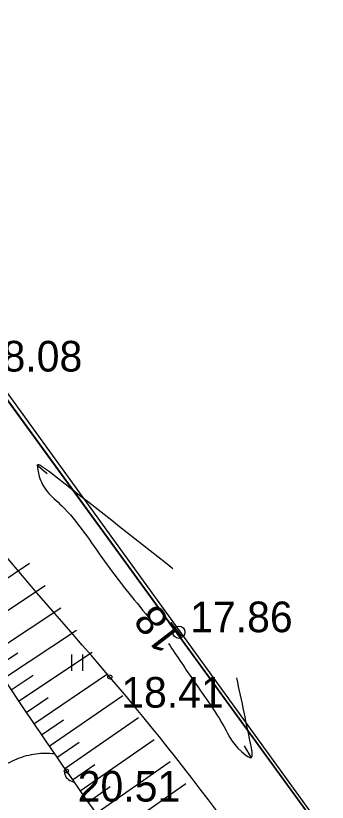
# Model space of a CAD drawing. Extents: x 521824 to 524158, y 294774 to 296228.
# Drawn here: x 522313.44 to 522324.88, y 296028.68 to 296057.55 of the extents above; entities that cross this region are included whole.
import ezdxf

# ---------------------------------------------------------------- set-up
doc = ezdxf.new("R2010")
doc.units = 0
for name, color, linetype in [('HIDG_AATZ_####_TKST_#', 7, 'Continuous'), ('HIDG_ELEM_####_####_#', 7, 'Continuous'), ('HIDG_HORZ_####_TKST_#', 7, 'Continuous'), ('HIDG_HORZ_RESN_####_#', 7, 'Continuous'), ('HIDG_PLIN_####_####_#', 7, 'Continuous'), ('RAMI_UZMR_####_####_#', 7, 'Continuous'), ('RELJ_AATZ_####_TKST_#', 7, 'Continuous'), ('RELJ_ELEM_####_####_#', 7, 'Continuous'), ('RELJ_HORZ_PAMT_####_#', 7, 'Continuous'), ('RELJ_HORZ_RESN_####_#', 7, 'Continuous'), ('RELJ_NOGA_####_####_#', 7, 'Continuous'), ('ROBZ_IERR_####_####_#', 7, 'Continuous'), ('TERT_ELEM_####_####_#', 7, 'Continuous')]:
    doc.layers.add(name, color=color, linetype=linetype)

msp = doc.modelspace()

# ---------------------------------------------------------------- linework, layer by layer
at = {"layer": 'HIDG_ELEM_####_####_#'}
msp.add_circle((522319.429, 296034.919), 0.225, dxfattribs=at)
at = {"layer": 'HIDG_HORZ_RESN_####_#'}
for p, q in [((522314.599, 296040.729), (522314.217, 296041.051)), ((522321.835, 296030.742), (522322.089, 296030.311))]:
    msp.add_line(p, q, dxfattribs=at)
for points in [[(522319.216, 296037.249), (522314.68, 296040.801), (522314.532, 296040.912), (522314.414, 296040.992), (522314.259, 296041.062), (522314.248, 296040.884), (522315.133, 296039.559), (522316.698, 296037.525), (522318.305, 296035.484)], [(522319.05, 296034.51), (522320.017, 296033.073), (522321.092, 296031.449), (522321.907, 296030.397), (522322.102, 296030.323), (522322.126, 296030.441), (522322.118, 296030.543), (522322.094, 296030.677), (522321.559, 296033.239)]]:
    msp.add_spline(points, degree=3, dxfattribs=at)
at = {"layer": 'HIDG_PLIN_####_####_#'}
msp.add_spline([(522371.644, 295960.784), (522368.316, 295964.419), (522361.623, 295972.484), (522354.568, 295982.304), (522351.14, 295981.353), (522353.628, 295983.369), (522349.258, 295989.963), (522348.612, 295994.653), (522338.197, 296003.541), (522326.066, 296020.438), (522316.898, 296033.274), (522306.811, 296047.683), (522300.907, 296055.765), (522298.65, 296054.773), (522297.679, 296054.56), (522296.95, 296056.439), (522297.579, 296057.714), (522297.352, 296058.697), (522297.043, 296059.475), (522296.096, 296061.4), (522294.24, 296064.18)], degree=3, dxfattribs=at)
at = {"layer": 'RAMI_UZMR_####_####_#'}
msp.add_lwpolyline([(522238.336, 296053.36), (522285.718, 296059.481), (522293.257, 296061.848), (522296.155, 296062.191), (522300.201, 296058.476), (522312.508, 296044.556), (522328.24, 296022.822), (522349.854, 295994.636), (522373.592, 295961.698), (522362.138, 295957.162), (522349.174, 295950.882), (522342.278, 295948.544), (522332.736, 295938.071), (522327.686, 295933.811), (522322.022, 295927.668), (522307.813, 295919.973), (522290.212, 295909.174), (522273.707, 295894.679), (522210.195, 295852.819)], dxfattribs=at)
at = {"layer": 'RELJ_ELEM_####_####_#'}
for centre in [(522316.898, 296033.274), (522315.3, 296029.826)]:
    msp.add_circle(centre, 0.075, dxfattribs=at)
at = {"layer": 'RELJ_HORZ_PAMT_####_#'}
msp.add_spline([(522315.604, 296029.396), (522315.24, 296029.699), (522315.251, 296029.819), (522315.303, 296029.833), (522315.332, 296029.807), (522315.604, 296029.396)], degree=3, dxfattribs=at)
at = {"layer": 'RELJ_HORZ_RESN_####_#'}
msp.add_spline([(522314.864, 296030.455), (522314.186, 296030.447), (522313.483, 296030.257), (522312.807, 296029.903), (522312.495, 296029.672), (522312.211, 296029.408), (522311.403, 296028.4), (522311.062, 296027.851), (522310.752, 296027.266), (522310.302, 296026.082), (522310.051, 296024.862), (522309.959, 296023.658), (522310.068, 296022.457), (522310.766, 296020.31), (522311.406, 296019.168), (522312.083, 296018.156)], degree=3, dxfattribs=at)
at = {"layer": 'RELJ_NOGA_####_####_#'}
for p, q in [((522311.339, 296035.722), (522313.945, 296037.455)), ((522311.891, 296034.889), (522314.525, 296036.629)), ((522312.443, 296034.054), (522315.101, 296035.81)), ((522312.994, 296033.22), (522315.676, 296034.995)), ((522312.718, 296033.637), (522313.519, 296034.167)), ((522313.548, 296032.388), (522316.246, 296034.191)), ((522313.271, 296032.803), (522314.078, 296033.34)), ((522314.108, 296031.559), (522316.811, 296033.396)), ((522314.673, 296030.734), (522317.379, 296032.599)), ((522313.828, 296031.973), (522314.637, 296032.52)), ((522315.241, 296029.911), (522317.956, 296031.79)), ((522314.39, 296031.146), (522315.202, 296031.701)), ((522314.957, 296030.322), (522315.77, 296030.883)), ((522315.812, 296029.09), (522318.531, 296030.984)), ((522315.526, 296029.5), (522316.341, 296030.066)), ((522316.384, 296028.269), (522319.11, 296030.174)), ((522316.098, 296028.679), (522316.915, 296029.249)), ((522316.957, 296027.45), (522319.688, 296029.363))]:
    msp.add_line(p, q, dxfattribs=at)
msp.add_spline([(522298.77, 296052.501), (522299.007, 296052.355), (522299.75, 296051.442), (522300.47, 296050.463), (522301.915, 296048.481), (522304.731, 296044.924), (522307.497, 296041.323), (522309.494, 296038.481), (522311.425, 296035.593), (522313.343, 296032.696), (522315.3, 296029.826), (522322.949, 296019.021), (522331.463, 296007.43), (522335.499, 296002.228)], degree=3, dxfattribs=at)
at = {"layer": 'ROBZ_IERR_####_####_#'}
for points in [[(522380.027, 296030.421), (522347.967, 296016.117), (522337.144, 296010.443), (522300.416, 296060.924), (522268.4, 296105.967)], [(521982.721, 296071.944), (522030.783, 296022.794), (522033.554, 296023.535), (522231.747, 296043.148), (522293.95, 296059.25), (522300.416, 296060.924), (522337.144, 296010.443), (522362.112, 295976.434), (522359.108, 295971.285), (522349.756, 295955.259), (522172.848, 295833.392), (522168.097, 295830.304), (522159.466, 295824.695), (522157.572, 295823.464), (522100.03, 295786.069), (522037.633, 295748.407), (521945.66, 295684.513), (521914.938, 295661.444)]]:
    msp.add_lwpolyline(points, dxfattribs=at)
at = {"layer": 'TERT_ELEM_####_####_#'}
for p, q in [((522315.5, 296033.5), (522315.5, 296034.1)), ((522315.9, 296033.5), (522315.9, 296034.1))]:
    msp.add_line(p, q, dxfattribs=at)

# ---------------------------------------------------------------- texts
at = {"layer": 'HIDG_AATZ_####_TKST_#'}
for s, p in [(' 18.08', (522311.703, 296044.489)), (' 17.86', (522319.429, 296034.919))]:
    msp.add_text(s, height=1.125, dxfattribs=at).set_placement(p)
at = {"layer": 'HIDG_HORZ_####_TKST_#'}
msp.add_text('18', height=1.125, rotation=127.5442, dxfattribs=at).set_placement((522319.624, 296034.695))
at = {"layer": 'RELJ_AATZ_####_TKST_#'}
for s, p in [(' 18.41', (522316.898, 296032.149)), (' 20.51', (522315.3, 296028.701))]:
    msp.add_text(s, height=1.125, dxfattribs=at).set_placement(p)

doc.saveas('drawing.dxf')
